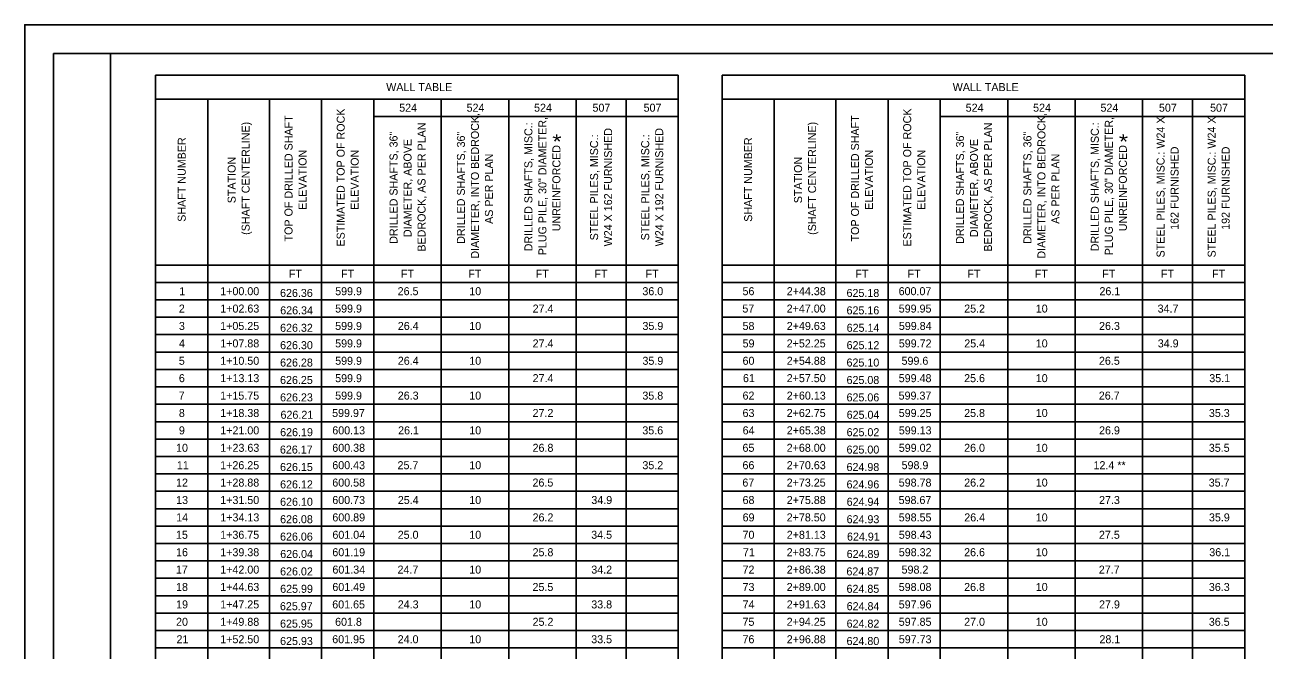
# Model space of a CAD drawing. Extents: x 0 to 34, y 0 to 22.
# Drawn here: x 0 to 21.68, y 11.06 to 22 of the extents above; entities that cross this region are included whole.
import ezdxf

# ---------------------------------------------------------------- set-up
doc = ezdxf.new("R2010")
doc.units = 0
for name, color, linetype in [('BR_P_Gen_Text', 7, 'Continuous'), ('SH_Border', 7, 'Continuous'), ('SH_Cut_Line', 7, 'Continuous')]:
    doc.layers.add(name, color=color, linetype=linetype)

msp = doc.modelspace()

# ---------------------------------------------------------------- linework, layer by layer
at = {"layer": 'BR_P_Gen_Text'}
for p, q in [((2.288, 21.12), (11.431, 21.12)), ((2.288, 21.12), (2.288, 0.754)), ((11.431, 21.12), (11.431, 0.754)), ((12.197, 21.12), (21.34, 21.12)), ((12.197, 21.12), (12.197, 0.754)), ((21.34, 21.12), (21.34, 0.754)), ((2.288, 20.702), (11.431, 20.702)), ((3.201, 20.702), (3.201, 0.754)), ((4.279, 20.702), (4.279, 0.754)), ((5.192, 20.702), (5.192, 0.754)), ((6.105, 20.702), (6.105, 0.754)), ((7.285, 20.702), (7.285, 0.754)), ((8.464, 20.702), (8.464, 0.754)), ((9.643, 20.702), (9.643, 0.754)), ((10.518, 20.702), (10.518, 0.754)), ((12.197, 20.702), (21.34, 20.702)), ((13.11, 20.702), (13.11, 0.754)), ((14.188, 20.702), (14.188, 0.754)), ((15.101, 20.702), (15.101, 0.754)), ((16.014, 20.702), (16.014, 0.754)), ((17.193, 20.702), (17.193, 0.754)), ((18.372, 20.702), (18.372, 0.754)), ((19.552, 20.702), (19.552, 0.754)), ((20.427, 20.702), (20.427, 0.754)), ((6.105, 20.398), (11.431, 20.398)), ((16.014, 20.398), (21.34, 20.398)), ((2.288, 17.798), (11.431, 17.798)), ((12.197, 17.798), (21.34, 17.798)), ((2.288, 17.494), (11.431, 17.494)), ((12.197, 17.494), (21.34, 17.494)), ((2.288, 17.189), (11.431, 17.189)), ((12.197, 17.189), (21.34, 17.189)), ((2.288, 16.885), (11.431, 16.885)), ((12.197, 16.885), (21.34, 16.885)), ((2.288, 16.581), (11.431, 16.581)), ((12.197, 16.581), (21.34, 16.581)), ((2.288, 16.276), (11.431, 16.276)), ((12.197, 16.276), (21.34, 16.276)), ((2.288, 15.972), (11.431, 15.972)), ((12.197, 15.972), (21.34, 15.972)), ((2.288, 15.668), (11.431, 15.668)), ((12.197, 15.668), (21.34, 15.668)), ((2.288, 15.363), (11.431, 15.363)), ((12.197, 15.363), (21.34, 15.363)), ((2.288, 15.059), (11.431, 15.059)), ((12.197, 15.059), (21.34, 15.059)), ((2.288, 14.754), (11.431, 14.754)), ((12.197, 14.754), (21.34, 14.754)), ((2.288, 14.45), (11.431, 14.45)), ((12.197, 14.45), (21.34, 14.45)), ((2.288, 14.146), (11.431, 14.146)), ((12.197, 14.146), (21.34, 14.146)), ((2.288, 13.841), (11.431, 13.841)), ((12.197, 13.841), (21.34, 13.841)), ((2.288, 13.537), (11.431, 13.537)), ((12.197, 13.537), (21.34, 13.537)), ((2.288, 13.233), (11.431, 13.233)), ((12.197, 13.233), (21.34, 13.233)), ((2.288, 12.928), (11.431, 12.928)), ((12.197, 12.928), (21.34, 12.928)), ((2.288, 12.624), (11.431, 12.624)), ((12.197, 12.624), (21.34, 12.624)), ((2.288, 12.32), (11.431, 12.32)), ((12.197, 12.32), (21.34, 12.32)), ((2.288, 12.015), (11.431, 12.015)), ((12.197, 12.015), (21.34, 12.015)), ((2.288, 11.711), (11.431, 11.711)), ((12.197, 11.711), (21.34, 11.711)), ((2.288, 11.407), (11.431, 11.407)), ((12.197, 11.407), (21.34, 11.407)), ((2.288, 11.102), (11.431, 11.102)), ((12.197, 11.102), (21.34, 11.102))]:
    msp.add_line(p, q, dxfattribs=at)
at = {"layer": 'SH_Border'}
for points in [[(0.5, 21.5), (1.5, 21.5), (1.5, 0.5), (0.5, 0.5)], [(1.5, 21.5), (33.5, 21.5), (33.5, 0.5), (1.5, 0.5)]]:
    msp.add_lwpolyline(points, close=True, dxfattribs=at)
at = {"layer": 'SH_Cut_Line'}
msp.add_lwpolyline([(0, 0), (34, 0), (34, 22), (0, 22)], close=True, dxfattribs=at)

# ---------------------------------------------------------------- texts
at = {"layer": 'BR_P_Gen_Text'}
for s, p in [('WALL TABLE', (6.322, 20.841)), ('WALL TABLE', (16.231, 20.841)), ('524', (6.549, 20.48)), ('524', (7.728, 20.48)), ('524', (8.908, 20.48)), ('507', (9.93, 20.48)), ('507', (10.824, 20.48)), ('524', (16.458, 20.48)), ('524', (17.637, 20.48)), ('524', (18.816, 20.48)), ('507', (19.839, 20.48)), ('507', (20.733, 20.48)), ('FT', (4.619, 17.576)), ('FT', (5.532, 17.576)), ('FT', (6.579, 17.576)), ('FT', (7.758, 17.576)), ('FT', (8.937, 17.576)), ('FT', (9.964, 17.576)), ('FT', (10.858, 17.576)), ('FT', (14.528, 17.576)), ('FT', (15.441, 17.576)), ('FT', (16.487, 17.576)), ('FT', (17.667, 17.576)), ('FT', (18.846, 17.576)), ('FT', (19.873, 17.576)), ('FT', (20.767, 17.576)), ('1', (2.702, 17.271)), ('1+00.00', (3.419, 17.271)), ('626.36', (4.465, 17.24)), ('599.9', (5.429, 17.271)), ('26.5', (6.522, 17.271)), ('10', (7.775, 17.271)), ('36.0', (10.803, 17.271)), ('56', (12.554, 17.271)), ('2+44.38', (13.328, 17.271)), ('625.18', (14.374, 17.24)), ('600.07', (15.285, 17.271)), ('26.1', (18.798, 17.271)), ('2', (2.695, 16.967)), ('1+02.63', (3.42, 16.967)), ('626.34', (4.468, 16.936)), ('599.9', (5.429, 16.967)), ('27.4', (8.883, 16.967)), ('57', (12.552, 16.967)), ('2+47.00', (13.327, 16.967)), ('625.16', (14.374, 16.936)), ('599.95', (15.287, 16.967)), ('25.2', (16.432, 16.967)), ('10', (17.684, 16.967)), ('34.7', (19.815, 16.967)), ('3', (2.696, 16.663)), ('1+05.25', (3.418, 16.663)), ('626.32', (4.466, 16.631)), ('599.9', (5.429, 16.663)), ('26.4', (6.525, 16.663)), ('10', (7.775, 16.663)), ('35.9', (10.804, 16.663)), ('58', (12.555, 16.663)), ('2+49.63', (13.328, 16.663)), ('625.14', (14.376, 16.631)), ('599.84', (15.289, 16.663)), ('26.3', (18.791, 16.663)), ('4', (2.697, 16.358)), ('1+07.88', (3.419, 16.358)), ('599.9', (5.429, 16.358)), ('27.4', (8.883, 16.358)), ('59', (12.556, 16.358)), ('2+52.25', (13.327, 16.358)), ('599.72', (15.288, 16.358)), ('25.4', (16.433, 16.358)), ('10', (17.684, 16.358)), ('34.9', (19.818, 16.358)), ('626.30', (4.466, 16.327)), ('625.12', (14.375, 16.327)), ('5', (2.694, 16.054)), ('1+10.50', (3.419, 16.054)), ('626.28', (4.466, 16.023)), ('599.9', (5.429, 16.054)), ('26.4', (6.525, 16.054)), ('10', (7.775, 16.054)), ('35.9', (10.804, 16.054)), ('60', (12.555, 16.054)), ('2+54.88', (13.328, 16.054)), ('625.10', (14.374, 16.023)), ('599.6', (15.336, 16.054)), ('26.5', (18.789, 16.054)), ('6', (2.695, 15.75)), ('1+13.13', (3.42, 15.75)), ('626.25', (4.465, 15.718)), ('599.9', (5.429, 15.75)), ('27.4', (8.883, 15.75)), ('61', (12.562, 15.75)), ('2+57.50', (13.327, 15.75)), ('625.08', (14.374, 15.718)), ('599.48', (15.287, 15.75)), ('25.6', (16.431, 15.75)), ('10', (17.684, 15.75)), ('35.1', (20.719, 15.75)), ('7', (2.692, 15.445)), ('1+15.75', (3.418, 15.445)), ('626.23', (4.466, 15.414)), ('599.9', (5.429, 15.445)), ('26.3', (6.524, 15.445)), ('10', (7.775, 15.445)), ('35.8', (10.803, 15.445)), ('62', (12.555, 15.445)), ('2+60.13', (13.328, 15.445)), ('625.06', (14.374, 15.414)), ('599.37', (15.285, 15.445)), ('26.7', (18.787, 15.445)), ('8', (2.695, 15.141)), ('1+18.38', (3.419, 15.141)), ('626.21', (4.473, 15.11)), ('599.97', (5.376, 15.141)), ('27.2', (8.882, 15.141)), ('63', (12.555, 15.141)), ('2+62.75', (13.327, 15.141)), ('625.04', (14.376, 15.11)), ('599.25', (15.287, 15.141)), ('25.8', (16.431, 15.141)), ('10', (17.684, 15.141)), ('35.3', (20.712, 15.141)), ('9', (2.696, 14.837)), ('1+21.00', (3.419, 14.837)), ('600.13', (5.379, 14.837)), ('26.1', (6.53, 14.837)), ('10', (7.775, 14.837)), ('35.6', (10.802, 14.837)), ('64', (12.556, 14.837)), ('2+65.38', (13.328, 14.837)), ('599.13', (15.288, 14.837)), ('26.9', (18.791, 14.837)), ('626.19', (4.467, 14.805)), ('625.02', (14.375, 14.805)), ('10', (2.646, 14.532)), ('1+23.63', (3.42, 14.532)), ('626.17', (4.463, 14.501)), ('600.38', (5.379, 14.532)), ('26.8', (8.882, 14.532)), ('65', (12.554, 14.532)), ('2+68.00', (13.327, 14.532)), ('625.00', (14.374, 14.501)), ('599.02', (15.288, 14.532)), ('26.0', (16.431, 14.532)), ('10', (17.684, 14.532)), ('35.5', (20.711, 14.532)), ('11', (2.66, 14.228)), ('1+26.25', (3.418, 14.228)), ('626.15', (4.465, 14.196)), ('600.43', (5.379, 14.228)), ('25.7', (6.52, 14.228)), ('10', (7.775, 14.228)), ('35.2', (10.803, 14.228)), ('66', (12.554, 14.228)), ('2+70.63', (13.328, 14.228)), ('624.98', (14.374, 14.196)), ('598.9', (15.337, 14.228)), ('12.4 **', (18.694, 14.228)), ('12', (2.646, 13.924)), ('1+28.88', (3.419, 13.924)), ('626.12', (4.466, 13.892)), ('600.58', (5.379, 13.924)), ('26.5', (8.881, 13.924)), ('67', (12.552, 13.924)), ('2+73.25', (13.327, 13.924)), ('624.96', (14.374, 13.892)), ('598.78', (15.287, 13.924)), ('26.2', (16.432, 13.924)), ('10', (17.684, 13.924)), ('35.7', (20.709, 13.924)), ('13', (2.647, 13.619)), ('1+31.50', (3.419, 13.619)), ('626.10', (4.466, 13.588)), ('600.73', (5.379, 13.619)), ('25.4', (6.525, 13.619)), ('10', (7.775, 13.619)), ('34.9', (9.91, 13.619)), ('68', (12.555, 13.619)), ('2+75.88', (13.328, 13.619)), ('624.94', (14.376, 13.588)), ('598.67', (15.285, 13.619)), ('27.3', (18.791, 13.619)), ('14', (2.648, 13.315)), ('1+34.13', (3.42, 13.315)), ('600.89', (5.38, 13.315)), ('26.2', (8.882, 13.315)), ('69', (12.556, 13.315)), ('2+78.50', (13.327, 13.315)), ('598.55', (15.287, 13.315)), ('26.4', (16.433, 13.315)), ('10', (17.684, 13.315)), ('35.9', (20.713, 13.315)), ('626.08', (4.466, 13.283)), ('624.93', (14.375, 13.283)), ('15', (2.645, 13.011)), ('1+36.75', (3.418, 13.011)), ('626.06', (4.465, 12.979)), ('601.04', (5.381, 13.011)), ('25.0', (6.523, 13.011)), ('10', (7.775, 13.011)), ('34.5', (9.908, 13.011)), ('70', (12.555, 13.011)), ('2+81.13', (13.328, 13.011)), ('624.91', (14.382, 12.979)), ('598.43', (15.288, 13.011)), ('27.5', (18.789, 13.011)), ('16', (2.646, 12.706)), ('1+39.38', (3.419, 12.706)), ('626.04', (4.468, 12.675)), ('601.19', (5.38, 12.706)), ('25.8', (8.882, 12.706)), ('71', (12.562, 12.706)), ('2+83.75', (13.327, 12.706)), ('624.89', (14.376, 12.675)), ('598.32', (15.288, 12.706)), ('26.6', (16.431, 12.706)), ('10', (17.684, 12.706)), ('36.1', (20.719, 12.706)), ('17', (2.643, 12.402)), ('1+42.00', (3.419, 12.402)), ('626.02', (4.466, 12.37)), ('601.34', (5.381, 12.402)), ('24.7', (6.52, 12.402)), ('10', (7.775, 12.402)), ('34.2', (9.909, 12.402)), ('72', (12.555, 12.402)), ('2+86.38', (13.328, 12.402)), ('624.87', (14.372, 12.37)), ('598.2', (15.337, 12.402)), ('27.7', (18.787, 12.402)), ('18', (2.646, 12.098)), ('1+44.63', (3.42, 12.098)), ('625.99', (4.467, 12.066)), ('601.49', (5.38, 12.098)), ('25.5', (8.881, 12.098)), ('73', (12.555, 12.098)), ('2+89.00', (13.327, 12.098)), ('624.85', (14.374, 12.066)), ('598.08', (15.287, 12.098)), ('26.8', (16.431, 12.098)), ('10', (17.684, 12.098)), ('36.3', (20.712, 12.098)), ('19', (2.647, 11.793)), ('1+47.25', (3.418, 11.793)), ('601.65', (5.378, 11.793)), ('24.3', (6.524, 11.793)), ('10', (7.775, 11.793)), ('33.8', (9.909, 11.793)), ('74', (12.556, 11.793)), ('2+91.63', (13.328, 11.793)), ('597.96', (15.287, 11.793)), ('27.9', (18.791, 11.793)), ('625.97', (4.463, 11.762)), ('624.84', (14.376, 11.762)), ('20', (2.646, 11.489)), ('1+49.88', (3.419, 11.489)), ('625.95', (4.465, 11.457)), ('601.8', (5.428, 11.489)), ('25.2', (8.882, 11.489)), ('75', (12.554, 11.489)), ('2+94.25', (13.327, 11.489)), ('624.82', (14.375, 11.457)), ('597.85', (15.287, 11.489)), ('27.0', (16.431, 11.489)), ('10', (17.684, 11.489)), ('36.5', (20.711, 11.489)), ('21', (2.654, 11.184)), ('1+52.50', (3.419, 11.184)), ('625.93', (4.466, 11.153)), ('601.95', (5.378, 11.184)), ('24.0', (6.523, 11.184)), ('10', (7.775, 11.184)), ('33.5', (9.908, 11.184)), ('76', (12.554, 11.184)), ('2+96.88', (13.328, 11.184)), ('624.80', (14.374, 11.153)), ('597.73', (15.288, 11.184)), ('28.1', (18.798, 11.184))]:
    msp.add_text(s, height=0.14, dxfattribs=at).set_placement(p)
for s, height, rotation, p in [('TOP OF DRILLED SHAFT ', 0.14, 90, (4.683, 18.211)), ('ESTIMATED TOP OF ROCK ', 0.14, 90, (5.596, 18.122)), ('DIAMETER, INTO BEDROCK, ', 0.14, 90, (7.944, 17.91)), ('TOP OF DRILLED SHAFT ', 0.14, 90, (14.592, 18.211)), ('ESTIMATED TOP OF ROCK ', 0.14, 90, (15.505, 18.122)), ('DIAMETER, INTO BEDROCK, ', 0.14, 90, (17.853, 17.91)), ('STEEL PILES, MISC.: W24 X ', 0.14, 90, (19.937, 17.931)), ('STEEL PILES, MISC.: W24 X ', 0.14, 90, (20.831, 17.931)), ('(SHAFT CENTERLINE)', 0.14, 90, (3.933, 18.326)), ('BEDROCK, AS PER PLAN', 0.14, 90, (7.01, 18.033)), ('DRILLED SHAFTS, MISC.: ', 0.14, 90, (8.879, 18.038)), ('PLUG PILE, 30" DIAMETER, ', 0.14, 90, (9.124, 17.97)), ('W24 X 162 FURNISHED', 0.14, 90, (10.273, 18.125)), ('W24 X 192 FURNISHED', 0.14, 90, (11.167, 18.125)), ('(SHAFT CENTERLINE)', 0.14, 90, (13.841, 18.326)), ('BEDROCK, AS PER PLAN', 0.14, 90, (16.918, 18.033)), ('DRILLED SHAFTS, MISC.: ', 0.14, 90, (18.787, 18.038)), ('PLUG PILE, 30" DIAMETER, ', 0.14, 90, (19.032, 17.97)), ('SHAFT NUMBER', 0.14, 90, (2.815, 18.555)), ('DRILLED SHAFTS, 36" ', 0.14, 90, (6.52, 18.17)), ('DIAMETER, ABOVE ', 0.14, 90, (6.765, 18.287)), ('DRILLED SHAFTS, 36" ', 0.14, 90, (7.699, 18.17)), ('*', 0.28, 73.734, (9.485, 19.89)), ('STEEL PILES, MISC.:                                          ', 0.14, 90, (10.028, 18.23)), ('STEEL PILES, MISC.:                                          ', 0.14, 90, (10.922, 18.23)), ('SHAFT NUMBER', 0.14, 90, (12.723, 18.555)), ('DRILLED SHAFTS, 36" ', 0.14, 90, (16.428, 18.17)), ('DIAMETER, ABOVE ', 0.14, 90, (16.673, 18.287)), ('DRILLED SHAFTS, 36" ', 0.14, 90, (17.608, 18.17)), ('*', 0.28, 73.734, (19.395, 19.89)), ('ELEVATION', 0.14, 90, (4.928, 18.764)), ('ELEVATION', 0.14, 90, (5.841, 18.764)), ('AS PER PLAN', 0.14, 90, (8.189, 18.518)), ('UNREINFORCED', 0.14, 90, (9.369, 18.389)), ('ELEVATION', 0.14, 90, (14.837, 18.764)), ('ELEVATION', 0.14, 90, (15.75, 18.764)), ('AS PER PLAN', 0.14, 90, (18.098, 18.518)), ('UNREINFORCED', 0.14, 90, (19.277, 18.389)), ('162 FURNISHED', 0.14, 90, (20.182, 18.414)), ('192 FURNISHED', 0.14, 90, (21.076, 18.414)), ('STATION                                                           ', 0.14, 90, (3.688, 18.879)), ('STATION                                                           ', 0.14, 90, (13.596, 18.879))]:
    msp.add_text(s, height=height, rotation=rotation, dxfattribs=at).set_placement(p)

doc.saveas('drawing.dxf')
